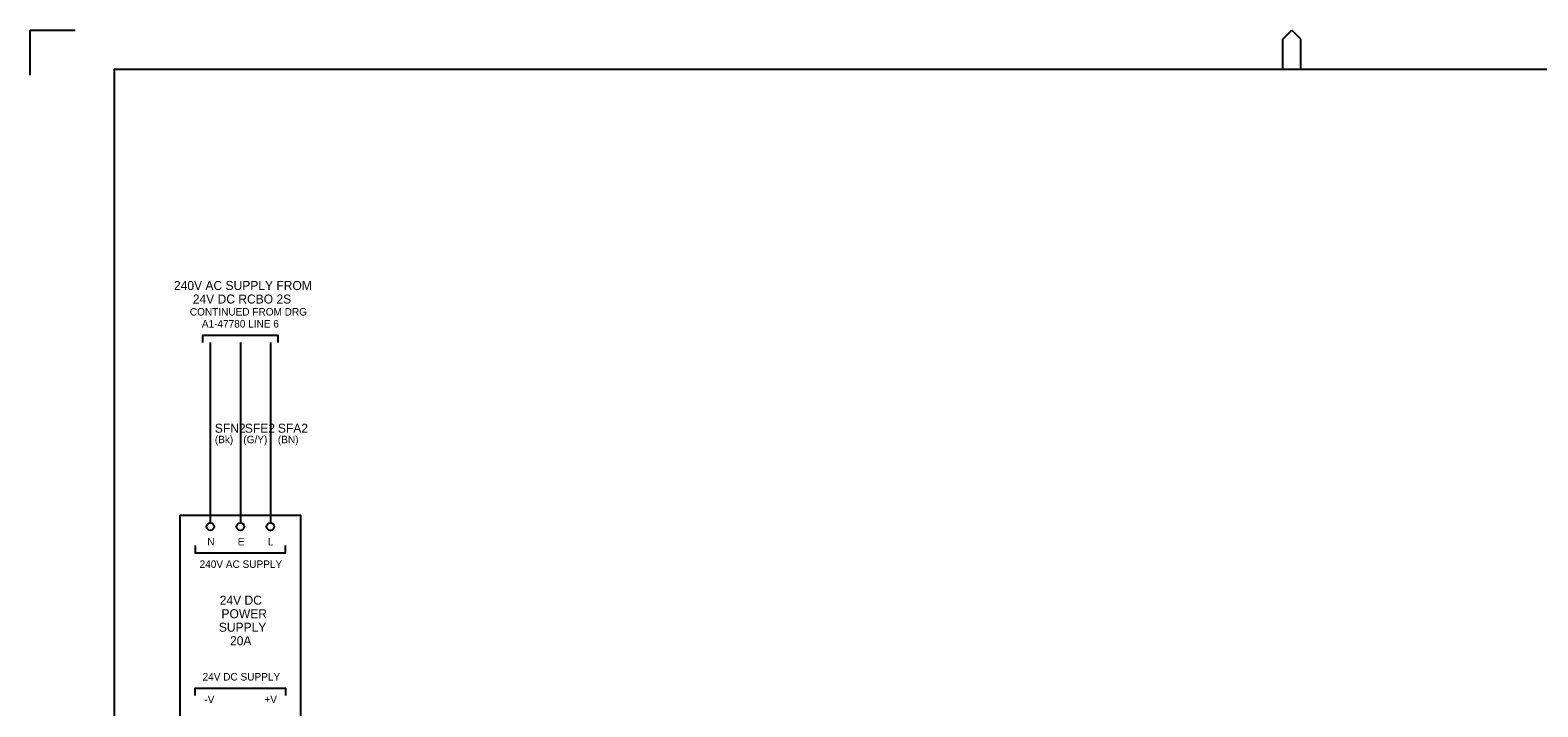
# Model space of a CAD drawing. Extents: x 0 to 841, y 0 to 594.
# Drawn here: x 0 to 502, y 369 to 594 of the extents above; entities that cross this region are included whole.
import ezdxf

# ---------------------------------------------------------------- set-up
doc = ezdxf.new("R2010")
doc.units = 0
for name, color, linetype in [('A1BORDER', 7, 'Continuous'), ('Level 1', 7, 'Continuous'), ('Level 4', 7, 'Continuous')]:
    doc.layers.add(name, color=color, linetype=linetype)

msp = doc.modelspace()

# ---------------------------------------------------------------- linework, layer by layer
at = {"layer": 'A1BORDER'}
for p, q in [((0, 594), (15, 594)), ((0, 579), (0, 594)), ((417.19, 591), (420.19, 594)), ((423.19, 591), (420.19, 594)), ((417.19, 581), (417.19, 591)), ((423.19, 581), (423.19, 591)), ((28, 581), (829, 581)), ((28, 581), (28, 15))]:
    msp.add_line(p, q, dxfattribs=at)
at = {"layer": 'Level 1'}
for p, q in [((60, 490), (60, 430)), ((70, 490), (70, 430)), ((80, 490), (80, 430))]:
    msp.add_line(p, q, dxfattribs=at)
for points in [[(57.5, 490), (57.5, 492.5), (82.5, 492.5), (82.5, 490)], [(55, 422.5), (55, 420), (85, 420), (85, 422.5)], [(55, 372.5), (55, 375), (85, 375), (85, 372.5)]]:
    msp.add_lwpolyline(points, dxfattribs=at)
msp.add_lwpolyline([(50, 432.5), (90, 432.5), (90, 362.5), (50, 362.5)], close=True, dxfattribs=at)
at = {"layer": 'Level 4'}
for centre in [(60, 428.75), (70, 428.75), (80, 428.75)]:
    msp.add_circle(centre, 1.25, dxfattribs=at)

# ---------------------------------------------------------------- texts
at = {"layer": 'Level 1'}
for s, height, p in [('240V AC SUPPLY FROM', 3, (47.89, 507.5)), ('24V DC RCBO 2S', 3, (54.16, 503)), ('CONTINUED FROM DRG', 2.5, (53.19, 499)), ('A1-47780 LINE 6', 2.5, (57.18, 495)), ('SFN2', 3, (61.5, 460)), ('SFE2', 3, (71.5, 460)), ('SFA2', 3, (82.5, 460)), ('(Bk)', 2.5, (61.5, 456.5)), ('(G/Y)', 2.5, (71, 456.5)), ('(BN)', 2.5, (82.5, 456.5)), ('N', 2.5, (59, 422.5)), ('E', 2.5, (69.13, 422.5)), ('L', 2.5, (79.13, 422.5)), ('240V AC SUPPLY', 2.5, (56.43, 415)), ('24V DC', 3, (63.13, 402.75)), ('SUPPLY', 3, (62.83, 393.75)), ('POWER', 3, (63.72, 398.25)), ('20A', 3, (66.56, 389.25)), ('24V DC SUPPLY', 2.5, (57.42, 377.5)), ('-V', 2.5, (58.01, 370)), ('+V', 2.5, (78.01, 370))]:
    msp.add_text(s, height=height, dxfattribs=at).set_placement(p)

doc.saveas('drawing.dxf')
